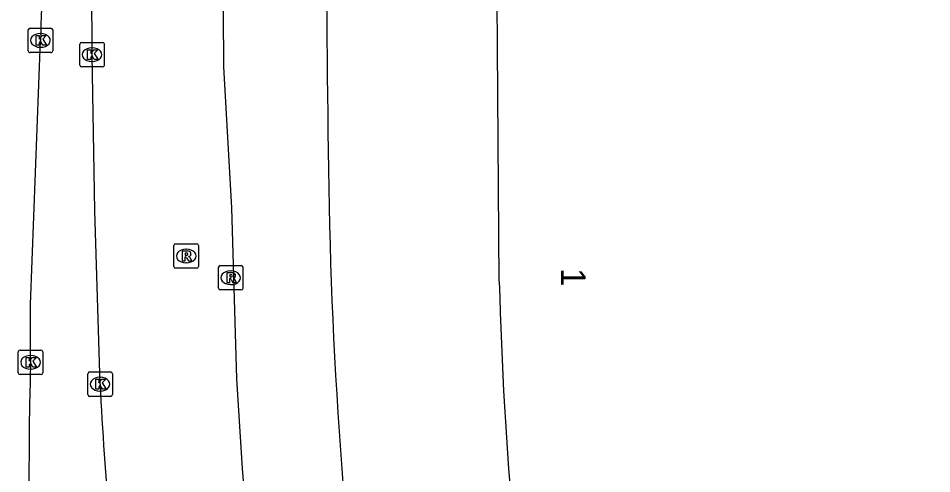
# Model space of a CAD drawing. Extents: x 155018 to 156648, y 383980 to 385733.
# Drawn here: x 155878.14 to 155915.42, y 385034.29 to 385052.88 of the extents above; entities that cross this region are included whole.
import ezdxf

# ---------------------------------------------------------------- set-up
doc = ezdxf.new("R2010")
doc.units = 0
for name, color, linetype in [('IMGEO_Kolk', 7, 'Continuous'), ('IMGEO_Pand', 7, 'Continuous'), ('IMGEO_Pand_nummerreeks', 7, 'Continuous'), ('IMGEO_Parkeervlak_gesloten', 7, 'Continuous'), ('IMGEO_Rijbaan_lokaal_gesloten', 7, 'Continuous'), ('IMGEO_Rijbaan_regionaal_gesloten', 7, 'Continuous'), ('IMGEO_Rioolput', 7, 'Continuous'), ('IMGEO_Voetpad_gesloten', 7, 'Continuous'), ('IMGEO_Voetpad_open', 7, 'Continuous')]:
    doc.layers.add(name, color=color, linetype=linetype)

msp = doc.modelspace()

# ---------------------------------------------------------------- linework, layer by layer
at = {"layer": 'IMGEO_Kolk'}
for p, q in [((155878.549, 385051.547), (155878.549, 385052.399)), ((155878.624, 385052.473), (155879.476, 385052.473)), ((155879.55, 385052.399), (155879.55, 385051.547)), ((155879.037, 385052.253), (155879.062, 385052.253)), ((155879.06, 385051.693), (155879.035, 385051.693)), ((155880.654, 385050.965), (155880.654, 385051.817)), ((155880.729, 385051.891), (155881.581, 385051.891)), ((155881.142, 385051.671), (155881.167, 385051.671)), ((155881.655, 385051.817), (155881.655, 385050.965)), ((155879.476, 385051.473), (155878.624, 385051.473)), ((155881.581, 385050.891), (155880.729, 385050.891)), ((155881.165, 385051.111), (155881.14, 385051.111)), ((155878.218, 385039.336), (155879.07, 385039.336)), ((155878.143, 385038.41), (155878.143, 385039.262)), ((155878.631, 385039.116), (155878.656, 385039.116)), ((155879.144, 385039.262), (155879.144, 385038.41)), ((155879.07, 385038.336), (155878.218, 385038.336)), ((155878.654, 385038.556), (155878.629, 385038.556)), ((155880.981, 385037.519), (155880.981, 385038.371)), ((155881.056, 385038.445), (155881.908, 385038.445)), ((155881.469, 385038.225), (155881.494, 385038.225)), ((155881.982, 385038.371), (155881.982, 385037.519)), ((155881.908, 385037.445), (155881.056, 385037.445)), ((155881.492, 385037.665), (155881.467, 385037.665))]:
    msp.add_line(p, q, dxfattribs=at)
for points in [[(155878.549, 385051.547), (155878.549, 385052.399)], [(155878.624, 385052.473), (155879.476, 385052.473)], [(155879.55, 385052.399), (155879.55, 385051.547)], [(155878.87, 385052.173), (155878.993, 385052.173), (155878.993, 385052.022), (155879.123, 385052.173), (155879.287, 385052.173), (155879.141, 385052.022), (155879.294, 385051.773), (155879.142, 385051.773), (155879.057, 385051.937), (155878.993, 385051.87), (155878.993, 385051.773), (155878.87, 385051.773), (155878.87, 385052.173)], [(155880.654, 385050.965), (155880.654, 385051.817)], [(155880.729, 385051.891), (155881.581, 385051.891)], [(155881.655, 385051.817), (155881.655, 385050.965)], [(155879.476, 385051.473), (155878.624, 385051.473)], [(155880.975, 385051.591), (155881.098, 385051.591), (155881.098, 385051.44), (155881.228, 385051.591), (155881.392, 385051.591), (155881.246, 385051.44), (155881.399, 385051.191), (155881.247, 385051.191), (155881.162, 385051.355), (155881.098, 385051.288), (155881.098, 385051.191), (155880.975, 385051.191), (155880.975, 385051.591)], [(155881.581, 385050.891), (155880.729, 385050.891)], [(155878.218, 385039.336), (155879.07, 385039.336)], [(155878.143, 385038.41), (155878.143, 385039.262)], [(155878.464, 385039.036), (155878.587, 385039.036), (155878.587, 385038.885), (155878.717, 385039.036), (155878.881, 385039.036), (155878.735, 385038.885), (155878.888, 385038.636), (155878.736, 385038.636), (155878.651, 385038.8), (155878.587, 385038.733), (155878.587, 385038.636), (155878.464, 385038.636), (155878.464, 385039.036)], [(155879.144, 385039.262), (155879.144, 385038.41)], [(155879.07, 385038.336), (155878.218, 385038.336)], [(155880.981, 385037.519), (155880.981, 385038.371)], [(155881.056, 385038.445), (155881.908, 385038.445)], [(155881.982, 385038.371), (155881.982, 385037.519)], [(155881.302, 385038.145), (155881.425, 385038.145), (155881.425, 385037.994), (155881.555, 385038.145), (155881.719, 385038.145), (155881.573, 385037.994), (155881.726, 385037.745), (155881.574, 385037.745), (155881.489, 385037.909), (155881.425, 385037.842), (155881.425, 385037.745), (155881.302, 385037.745), (155881.302, 385038.145)], [(155881.908, 385037.445), (155881.056, 385037.445)]]:
    msp.add_lwpolyline(points, dxfattribs=at)
for centre, start, end in [((155878.626, 385052.397), 91.552, 178.448), ((155878.626, 385052.397), 91.552, 178.448), ((155879.474, 385052.397), 1.552, 88.448), ((155879.474, 385052.397), 1.552, 88.448), ((155880.731, 385051.815), 91.552, 178.448), ((155880.731, 385051.815), 91.552, 178.448), ((155881.579, 385051.815), 1.552, 88.448), ((155881.579, 385051.815), 1.552, 88.448), ((155878.626, 385051.549), 181.552, 268.448), ((155878.626, 385051.549), 181.552, 268.448), ((155879.474, 385051.549), 271.552, 358.448), ((155879.474, 385051.549), 271.552, 358.448), ((155880.731, 385050.967), 181.552, 268.448), ((155880.731, 385050.967), 181.552, 268.448), ((155881.579, 385050.967), 271.552, 358.448), ((155881.579, 385050.967), 271.552, 358.448), ((155878.22, 385039.26), 91.552, 178.448), ((155878.22, 385039.26), 91.552, 178.448), ((155879.068, 385039.26), 1.552, 88.448), ((155879.068, 385039.26), 1.552, 88.448), ((155878.22, 385038.412), 181.552, 268.448), ((155878.22, 385038.412), 181.552, 268.448), ((155879.068, 385038.412), 271.552, 358.448), ((155879.068, 385038.412), 271.552, 358.448), ((155881.058, 385038.369), 91.552, 178.448), ((155881.058, 385038.369), 91.552, 178.448), ((155881.906, 385038.369), 1.552, 88.448), ((155881.906, 385038.369), 1.552, 88.448), ((155881.058, 385037.521), 181.552, 268.448), ((155881.058, 385037.521), 181.552, 268.448), ((155881.906, 385037.521), 271.552, 358.448), ((155881.906, 385037.521), 271.552, 358.448)]:
    msp.add_arc(centre, 0.0765, start, end, dxfattribs=at)
for centre, major_axis, ratio, start_param, end_param in [((155879.036, 385051.973), (-0.387, 0.002), 0.722429, 4.712389, 7.853982), ((155879.061, 385051.973), (-0.39, 0.002), 0.717154, 1.570796, 4.712389), ((155881.141, 385051.391), (-0.387, 0.002), 0.722429, 4.712389, 7.853982), ((155881.166, 385051.391), (-0.39, 0.002), 0.717154, 1.570796, 4.712389), ((155878.63, 385038.836), (-0.387, 0.002), 0.722429, 4.712389, 7.853982), ((155878.655, 385038.836), (-0.39, 0.002), 0.717154, 1.570796, 4.712389), ((155881.468, 385037.945), (-0.387, 0.002), 0.722429, 4.712389, 7.853982), ((155881.493, 385037.945), (-0.39, 0.002), 0.717154, 1.570796, 4.712389)]:
    msp.add_ellipse(centre, major_axis=major_axis, ratio=ratio, start_param=start_param, end_param=end_param, dxfattribs=at)
at = {"layer": 'IMGEO_Pand'}
msp.add_lwpolyline([(155897.771, 385042.136), (155897.611, 385063.175)], dxfattribs=at)
msp.add_arc((156055.177, 385046.103), 157.456, 181.44355, 188.86745, dxfattribs=at)
at = {"layer": 'IMGEO_Parkeervlak_gesloten'}
msp.add_lwpolyline([(155881.482, 385037.945), (155881.273, 385045.012), (155881.155, 385051.391), (155881.105, 385062.386)], dxfattribs=at)
msp.add_arc((156051.541, 385046.491), 170.274, 182.87693, 186.73665, dxfattribs=at)
at = {"layer": 'IMGEO_Rijbaan_lokaal_gesloten'}
msp.add_lwpolyline([(155886.445, 385062.008), (155886.515, 385050.897), (155886.842, 385045.146), (155887.048, 385038.168), (155887.274, 385034.508), (155887.582, 385030.854), (155887.97, 385027.207), (155888.606, 385022.586), (155889.293, 385017.973), (155890.031, 385013.367), (155890.375, 385011.468), (155890.518, 385010.938), (155890.918, 385009.091), (155891.359, 385007.254), (155891.842, 385005.427), (155893.925, 384997.709), (155895.33, 384992.84)], dxfattribs=at)
for centre, radius, start, end in [((156337.892, 385055.345), 447.168, 177.90014, 181.00859), ((156083.097, 385049.125), 192.311, 180.49177, 187.78196)]:
    msp.add_arc(centre, radius, start, end, dxfattribs=at)
at = {"layer": 'IMGEO_Rijbaan_regionaal_gesloten'}
msp.add_lwpolyline([(155878.647, 385038.954), (155878.636, 385041.197), (155879.05, 385051.973)], dxfattribs=at)
for centre, radius, start, end in [((155938.845, 385050.599), 59.811, 173.6602, 178.68403), ((156092.969, 385033.363), 214.395, 178.50567, 186.41147)]:
    msp.add_arc(centre, radius, start, end, dxfattribs=at)
at = {"layer": 'IMGEO_Rioolput'}
for p, q in [((155884.495, 385042.748), (155884.495, 385043.6)), ((155884.57, 385043.674), (155885.422, 385043.674)), ((155884.983, 385043.454), (155885.008, 385043.454)), ((155885.496, 385043.6), (155885.496, 385042.748)), ((155885.422, 385042.674), (155884.57, 385042.674)), ((155885.006, 385042.894), (155884.981, 385042.894)), ((155886.312, 385041.863), (155886.312, 385042.715)), ((155886.387, 385042.789), (155887.239, 385042.789)), ((155887.313, 385042.715), (155887.313, 385041.863)), ((155886.8, 385042.569), (155886.825, 385042.569)), ((155886.823, 385042.009), (155886.798, 385042.009)), ((155887.239, 385041.789), (155886.387, 385041.789))]:
    msp.add_line(p, q, dxfattribs=at)
for points in [[(155884.495, 385042.748), (155884.495, 385043.6)], [(155884.57, 385043.674), (155885.422, 385043.674)], [(155885.496, 385043.6), (155885.496, 385042.748)], [(155885.084, 385043.372), (155884.832, 385043.374), (155884.832, 385042.974)], [(155884.832, 385042.974), (155884.956, 385042.974), (155884.956, 385043.136), (155884.967, 385043.136)], [(155885.01, 385043.293), (155884.956, 385043.293), (155884.956, 385043.212)], [(155884.956, 385043.212), (155885.008, 385043.212)], [(155885.014, 385043.107), (155885.085, 385042.974), (155885.225, 385042.974), (155885.16, 385043.1)], [(155885.422, 385042.674), (155884.57, 385042.674)], [(155886.312, 385041.863), (155886.312, 385042.715)], [(155886.387, 385042.789), (155887.239, 385042.789)], [(155887.313, 385042.715), (155887.313, 385041.863)], [(155886.901, 385042.487), (155886.649, 385042.489), (155886.649, 385042.089)], [(155886.827, 385042.408), (155886.773, 385042.408), (155886.773, 385042.327)], [(155886.773, 385042.327), (155886.825, 385042.327)], [(155886.649, 385042.089), (155886.773, 385042.089), (155886.773, 385042.251), (155886.784, 385042.251)], [(155886.831, 385042.222), (155886.902, 385042.089), (155887.042, 385042.089), (155886.977, 385042.215)], [(155887.239, 385041.789), (155886.387, 385041.789)]]:
    msp.add_lwpolyline(points, dxfattribs=at)
for centre, radius, start, end in [((155884.572, 385043.598), 0.0765, 91.552, 178.448), ((155884.572, 385043.598), 0.0765, 91.552, 178.448), ((155885.42, 385043.598), 0.0765, 1.552, 88.448), ((155885.42, 385043.598), 0.0765, 1.552, 88.448), ((155884.966, 385043.083), 0.0533, 26.0293, 88.6989), ((155884.992, 385043.401), 0.19, 274.7715, 282.9687), ((155885.016, 385043.197), 0.0964, 77.0061, 93.1865), ((155885.03, 385043.254), 0.0378, 276.6634, 79.6772), ((155885.083, 385043.262), 0.109, 350.3612, 89.416), ((155885.081, 385043.262), 0.112, 277.5842, 350.9817), ((155885.065, 385043.047), 0.108, 29.5134, 73.7905), ((155884.572, 385042.75), 0.0765, 181.552, 268.448), ((155884.572, 385042.75), 0.0765, 181.552, 268.448), ((155885.42, 385042.75), 0.0765, 271.552, 358.448), ((155885.42, 385042.75), 0.0765, 271.552, 358.448), ((155886.389, 385042.713), 0.0765, 91.552, 178.448), ((155886.389, 385042.713), 0.0765, 91.552, 178.448), ((155887.237, 385042.713), 0.0765, 1.552, 88.448), ((155887.237, 385042.713), 0.0765, 1.552, 88.448), ((155886.809, 385042.516), 0.19, 274.7715, 282.9687), ((155886.833, 385042.312), 0.0964, 77.0061, 93.1865), ((155886.847, 385042.369), 0.0378, 276.6634, 79.6772), ((155886.9, 385042.377), 0.109, 350.3612, 89.416), ((155886.898, 385042.377), 0.112, 277.5842, 350.9817), ((155886.783, 385042.198), 0.0533, 26.0293, 88.6989), ((155886.882, 385042.162), 0.108, 29.5134, 73.7905), ((155886.389, 385041.865), 0.0765, 181.552, 268.448), ((155886.389, 385041.865), 0.0765, 181.552, 268.448), ((155887.237, 385041.865), 0.0765, 271.552, 358.448), ((155887.237, 385041.865), 0.0765, 271.552, 358.448)]:
    msp.add_arc(centre, radius, start, end, dxfattribs=at)
for centre, major_axis, ratio, start_param, end_param in [((155884.982, 385043.174), (-0.387, 0.002), 0.722429, 4.712389, 7.853982), ((155885.007, 385043.174), (-0.39, 0.002), 0.717154, 1.570796, 4.712389), ((155886.799, 385042.289), (-0.387, 0.002), 0.722429, 4.712389, 7.853982), ((155886.824, 385042.289), (-0.39, 0.002), 0.717154, 1.570796, 4.712389)]:
    msp.add_ellipse(centre, major_axis=major_axis, ratio=ratio, start_param=start_param, end_param=end_param, dxfattribs=at)
at = {"layer": 'IMGEO_Voetpad_gesloten'}
msp.add_arc((155760.944, 384796.519), 312.012, 54.47286, 60.9796, dxfattribs=at)
at = {"layer": 'IMGEO_Voetpad_open'}
msp.add_arc((155856.355, 384950.813), 135.697, 47.5775, 64.2279, dxfattribs=at)

# ---------------------------------------------------------------- texts
at = {"layer": 'IMGEO_Pand_nummerreeks'}
msp.add_text('1', height=1, rotation=270.4357, dxfattribs=at).set_placement((155900.286, 385042.677))

doc.saveas('drawing.dxf')
